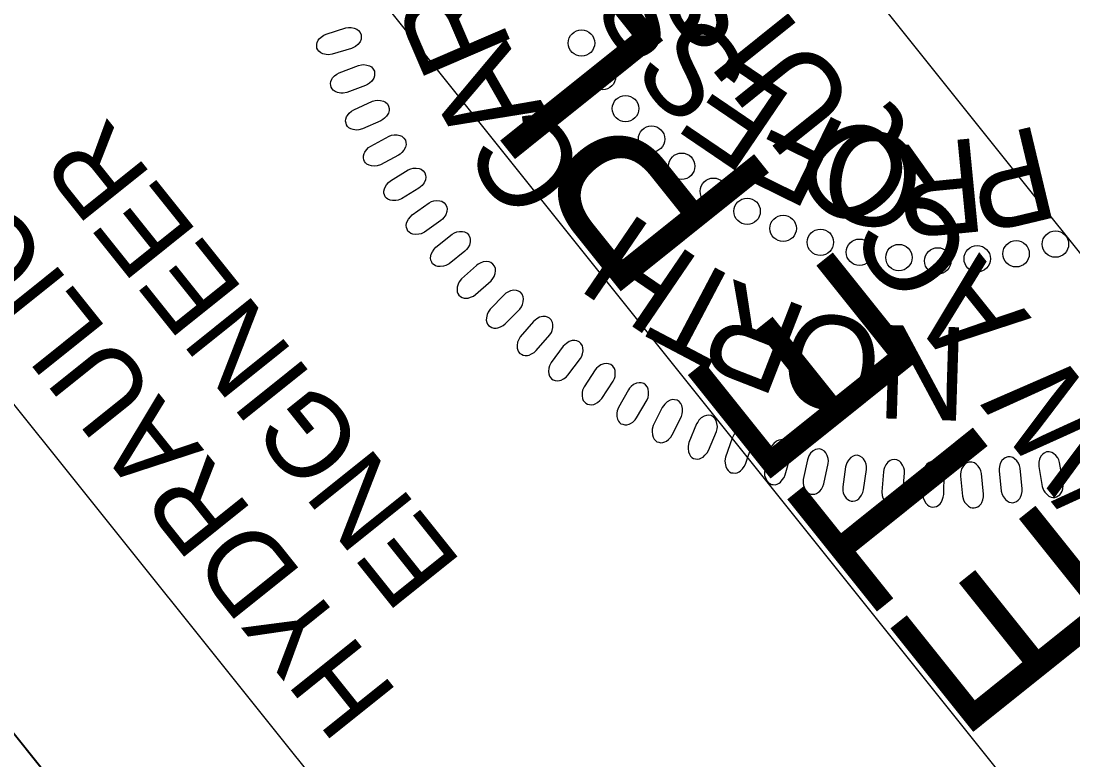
# Model space of a CAD drawing. Extents: x 473437 to 475344, y 504319 to 506318.
# Drawn here: x 473521.1 to 473584.9, y 505603.9 to 505648.7 of the extents above; entities that cross this region are included whole.
import ezdxf

# ---------------------------------------------------------------- set-up
doc = ezdxf.new("R2010")
doc.units = 0
for name, color, linetype in [('Sheet PE Seal Cell', 7, 'Continuous'), ('Sheet Plan CELL', 7, 'Continuous'), ('Sheet Sticker Incomplete CELL', 7, 'Continuous')]:
    doc.layers.add(name, color=color, linetype=linetype)

msp = doc.modelspace()

# ---------------------------------------------------------------- linework, layer by layer
at = {"layer": 'Sheet PE Seal Cell'}
for points in [[(473541.122, 505647.047), (473539.95, 505646.687), (473539.729, 505646.659), (473539.58, 505646.667), (473539.385, 505646.725), (473539.251, 505646.786), (473539.142, 505646.87), (473539.074, 505646.958), (473539.021, 505647.059), (473539.008, 505647.172), (473539.002, 505647.295), (473539.028, 505647.413), (473539.093, 505647.543), (473539.151, 505647.623), (473539.274, 505647.731), (473539.429, 505647.841), (473539.575, 505647.909), (473540.774, 505648.285), (473540.943, 505648.313), (473541.089, 505648.311), (473541.268, 505648.272), (473541.435, 505648.206), (473541.539, 505648.137), (473541.642, 505648.004), (473541.705, 505647.867), (473541.711, 505647.712), (473541.694, 505647.597), (473541.636, 505647.447), (473541.508, 505647.283), (473541.357, 505647.165), (473541.242, 505647.099)], [(473541.975, 505644.805), (473540.827, 505644.372), (473540.609, 505644.33), (473540.46, 505644.33), (473540.261, 505644.375), (473540.125, 505644.427), (473540.01, 505644.504), (473539.936, 505644.588), (473539.878, 505644.686), (473539.857, 505644.797), (473539.843, 505644.92), (473539.862, 505645.039), (473539.918, 505645.172), (473539.972, 505645.256), (473540.088, 505645.372), (473540.235, 505645.491), (473540.377, 505645.569), (473541.55, 505646.018), (473541.716, 505646.058), (473541.863, 505646.065), (473542.044, 505646.037), (473542.214, 505645.981), (473542.323, 505645.919), (473542.435, 505645.793), (473542.506, 505645.659), (473542.521, 505645.506), (473542.511, 505645.391), (473542.463, 505645.237), (473542.347, 505645.065), (473542.202, 505644.938), (473542.091, 505644.865)], [(473542.896, 505642.66), (473541.777, 505642.156), (473541.562, 505642.1), (473541.413, 505642.09), (473541.212, 505642.122), (473541.073, 505642.166), (473540.954, 505642.235), (473540.874, 505642.315), (473540.809, 505642.409), (473540.782, 505642.519), (473540.76, 505642.641), (473540.772, 505642.76), (473540.82, 505642.896), (473540.868, 505642.984), (473540.977, 505643.107), (473541.116, 505643.235), (473541.252, 505643.322), (473542.395, 505643.844), (473542.559, 505643.893), (473542.704, 505643.909), (473542.886, 505643.893), (473543.06, 505643.848), (473543.173, 505643.793), (473543.292, 505643.674), (473543.371, 505643.546), (473543.396, 505643.393), (473543.394, 505643.278), (473543.355, 505643.121), (473543.25, 505642.942), (473543.113, 505642.807), (473543.008, 505642.727)], [(473543.966, 505640.564), (473542.882, 505639.991), (473542.67, 505639.921), (473542.522, 505639.903), (473542.32, 505639.923), (473542.178, 505639.957), (473542.055, 505640.019), (473541.971, 505640.093), (473541.9, 505640.182), (473541.866, 505640.291), (473541.836, 505640.411), (473541.841, 505640.531), (473541.88, 505640.67), (473541.922, 505640.76), (473542.023, 505640.89), (473542.154, 505641.027), (473542.285, 505641.121), (473543.392, 505641.715), (473543.552, 505641.774), (473543.697, 505641.799), (473543.88, 505641.795), (473544.056, 505641.761), (473544.172, 505641.712), (473544.298, 505641.601), (473544.385, 505641.478), (473544.42, 505641.328), (473544.425, 505641.212), (473544.396, 505641.053), (473544.302, 505640.868), (473544.175, 505640.725), (473544.074, 505640.638)], [(473545.204, 505638.558), (473544.158, 505637.918), (473543.951, 505637.835), (473543.805, 505637.808), (473543.602, 505637.815), (473543.457, 505637.84), (473543.331, 505637.895), (473543.242, 505637.962), (473543.167, 505638.048), (473543.125, 505638.154), (473543.088, 505638.271), (473543.085, 505638.392), (473543.115, 505638.534), (473543.152, 505638.626), (473543.244, 505638.762), (473543.367, 505638.906), (473543.491, 505639.009), (473544.559, 505639.671), (473544.715, 505639.74), (473544.857, 505639.775), (473545.041, 505639.781), (473545.218, 505639.759), (473545.337, 505639.718), (473545.47, 505639.615), (473545.565, 505639.498), (473545.609, 505639.349), (473545.621, 505639.234), (473545.603, 505639.073), (473545.52, 505638.883), (473545.402, 505638.732), (473545.307, 505638.639)], [(473546.544, 505636.605), (473545.539, 505635.9), (473545.338, 505635.804), (473545.194, 505635.767), (473544.991, 505635.762), (473544.845, 505635.778), (473544.715, 505635.824), (473544.623, 505635.887), (473544.542, 505635.967), (473544.494, 505636.071), (473544.45, 505636.186), (473544.439, 505636.306), (473544.46, 505636.448), (473544.491, 505636.543), (473544.575, 505636.684), (473544.688, 505636.836), (473544.805, 505636.946), (473545.83, 505637.674), (473545.981, 505637.753), (473546.121, 505637.797), (473546.304, 505637.814), (473546.482, 505637.803), (473546.604, 505637.77), (473546.743, 505637.675), (473546.845, 505637.564), (473546.898, 505637.419), (473546.917, 505637.304), (473546.908, 505637.143), (473546.838, 505636.949), (473546.73, 505636.79), (473546.641, 505636.691)], [(473547.997, 505634.746), (473547.039, 505633.98), (473546.845, 505633.872), (473546.702, 505633.826), (473546.5, 505633.807), (473546.354, 505633.815), (473546.221, 505633.852), (473546.125, 505633.909), (473546.039, 505633.984), (473545.985, 505634.084), (473545.933, 505634.196), (473545.915, 505634.315), (473545.927, 505634.459), (473545.953, 505634.556), (473546.027, 505634.702), (473546.13, 505634.861), (473546.241, 505634.978), (473547.217, 505635.769), (473547.364, 505635.857), (473547.501, 505635.909), (473547.681, 505635.939), (473547.861, 505635.939), (473547.983, 505635.913), (473548.128, 505635.827), (473548.237, 505635.723), (473548.299, 505635.582), (473548.326, 505635.469), (473548.328, 505635.307), (473548.27, 505635.107), (473548.172, 505634.943), (473548.089, 505634.839)], [(473548.701, 505633.881), (473547.793, 505633.056), (473547.656, 505632.881), (473547.588, 505632.748), (473547.537, 505632.551), (473547.521, 505632.405), (473547.538, 505632.269), (473547.578, 505632.165), (473547.64, 505632.068), (473547.73, 505631.999), (473547.832, 505631.93), (473547.947, 505631.893), (473548.091, 505631.883), (473548.19, 505631.892), (473548.346, 505631.943), (473548.52, 505632.019), (473548.652, 505632.11), (473549.588, 505632.949), (473549.698, 505633.08), (473549.771, 505633.207), (473549.829, 505633.38), (473549.857, 505633.558), (473549.851, 505633.683), (473549.789, 505633.84), (473549.704, 505633.964), (473549.573, 505634.048), (473549.466, 505634.091), (473549.307, 505634.118), (473549.101, 505634.093), (473548.923, 505634.022), (473548.807, 505633.957)], [(473550.383, 505632.104), (473549.529, 505631.224), (473549.402, 505631.04), (473549.343, 505630.904), (473549.305, 505630.704), (473549.298, 505630.557), (473549.323, 505630.422), (473549.371, 505630.32), (473549.437, 505630.228), (473549.532, 505630.164), (473549.638, 505630.102), (473549.755, 505630.072), (473549.899, 505630.071), (473549.998, 505630.087), (473550.151, 505630.147), (473550.318, 505630.234), (473550.446, 505630.333), (473551.326, 505631.23), (473551.428, 505631.367), (473551.493, 505631.498), (473551.54, 505631.675), (473551.557, 505631.854), (473551.542, 505631.978), (473551.472, 505632.131), (473551.378, 505632.25), (473551.243, 505632.325), (473551.133, 505632.362), (473550.973, 505632.379), (473550.769, 505632.341), (473550.596, 505632.259), (473550.484, 505632.186)], [(473552.158, 505630.475), (473551.361, 505629.543), (473551.247, 505629.352), (473551.195, 505629.212), (473551.17, 505629.01), (473551.173, 505628.864), (473551.206, 505628.73), (473551.26, 505628.632), (473551.332, 505628.543), (473551.43, 505628.486), (473551.54, 505628.431), (473551.659, 505628.408), (473551.804, 505628.416), (473551.901, 505628.438), (473552.049, 505628.508), (473552.211, 505628.605), (473552.332, 505628.712), (473553.154, 505629.662), (473553.248, 505629.805), (473553.305, 505629.94), (473553.34, 505630.12), (473553.345, 505630.299), (473553.323, 505630.423), (473553.243, 505630.57), (473553.142, 505630.682), (473553.003, 505630.749), (473552.891, 505630.78), (473552.73, 505630.786), (473552.529, 505630.736), (473552.361, 505630.643), (473552.254, 505630.563)], [(473553.967, 505628.97), (473553.23, 505627.99), (473553.128, 505627.792), (473553.085, 505627.648), (473553.073, 505627.446), (473553.085, 505627.3), (473553.127, 505627.169), (473553.186, 505627.073), (473553.264, 505626.99), (473553.365, 505626.938), (473553.479, 505626.891), (473553.599, 505626.876), (473553.742, 505626.893), (473553.838, 505626.92), (473553.982, 505627), (473554.137, 505627.107), (473554.251, 505627.221), (473555.013, 505628.221), (473555.097, 505628.37), (473555.145, 505628.508), (473555.169, 505628.69), (473555.163, 505628.869), (473555.133, 505628.991), (473555.044, 505629.134), (473554.936, 505629.239), (473554.793, 505629.297), (473554.68, 505629.32), (473554.518, 505629.317), (473554.321, 505629.253), (473554.159, 505629.15), (473554.057, 505629.065)], [(473555.91, 505627.536), (473555.236, 505626.511), (473555.146, 505626.308), (473555.113, 505626.162), (473555.113, 505625.959), (473555.134, 505625.813), (473555.184, 505625.685), (473555.25, 505625.594), (473555.332, 505625.516), (473555.437, 505625.47), (473555.553, 505625.431), (473555.673, 505625.423), (473555.816, 505625.448), (473555.91, 505625.482), (473556.048, 505625.57), (473556.197, 505625.687), (473556.304, 505625.808), (473557, 505626.854), (473557.075, 505627.008), (473557.114, 505627.149), (473557.127, 505627.332), (473557.11, 505627.51), (473557.073, 505627.63), (473556.974, 505627.766), (473556.86, 505627.865), (473556.714, 505627.914), (473556.598, 505627.93), (473556.438, 505627.917), (473556.245, 505627.841), (473556.09, 505627.728), (473555.993, 505627.636)], [(473557.922, 505626.328), (473557.314, 505625.262), (473557.238, 505625.053), (473557.213, 505624.906), (473557.227, 505624.703), (473557.256, 505624.56), (473557.314, 505624.435), (473557.385, 505624.349), (473557.473, 505624.276), (473557.58, 505624.238), (473557.699, 505624.204), (473557.819, 505624.204), (473557.96, 505624.238), (473558.051, 505624.278), (473558.184, 505624.375), (473558.325, 505624.501), (473558.423, 505624.628), (473559.053, 505625.716), (473559.118, 505625.874), (473559.148, 505626.017), (473559.15, 505626.201), (473559.122, 505626.377), (473559.077, 505626.495), (473558.97, 505626.625), (473558.85, 505626.716), (473558.701, 505626.755), (473558.585, 505626.764), (473558.425, 505626.741), (473558.237, 505626.653), (473558.09, 505626.53), (473558, 505626.433)], [(473559.974, 505625.257), (473559.433, 505624.156), (473559.37, 505623.943), (473559.356, 505623.794), (473559.381, 505623.593), (473559.421, 505623.451), (473559.486, 505623.33), (473559.562, 505623.248), (473559.654, 505623.181), (473559.764, 505623.15), (473559.884, 505623.124), (473560.004, 505623.131), (473560.142, 505623.175), (473560.231, 505623.22), (473560.357, 505623.324), (473560.49, 505623.46), (473560.581, 505623.593), (473561.141, 505624.717), (473561.196, 505624.88), (473561.217, 505625.025), (473561.206, 505625.207), (473561.167, 505625.383), (473561.115, 505625.496), (473561.001, 505625.619), (473560.875, 505625.703), (473560.724, 505625.733), (473560.608, 505625.735), (473560.45, 505625.701), (473560.268, 505625.602), (473560.128, 505625.47), (473560.044, 505625.367)], [(473562.067, 505624.265), (473561.597, 505623.131), (473561.547, 505622.914), (473561.542, 505622.766), (473561.58, 505622.566), (473561.628, 505622.427), (473561.701, 505622.311), (473561.782, 505622.234), (473561.878, 505622.172), (473561.989, 505622.148), (473562.111, 505622.129), (473562.231, 505622.144), (473562.366, 505622.197), (473562.452, 505622.247), (473562.571, 505622.359), (473562.696, 505622.503), (473562.777, 505622.641), (473563.266, 505623.799), (473563.31, 505623.964), (473563.322, 505624.11), (473563.301, 505624.292), (473563.251, 505624.464), (473563.192, 505624.575), (473563.069, 505624.691), (473562.939, 505624.766), (473562.786, 505624.787), (473562.67, 505624.781), (473562.514, 505624.737), (473562.339, 505624.626), (473562.208, 505624.487), (473562.131, 505624.378)], [(473564.219, 505623.403), (473563.821, 505622.243), (473563.785, 505622.023), (473563.789, 505621.874), (473563.839, 505621.677), (473563.896, 505621.542), (473563.976, 505621.43), (473564.062, 505621.358), (473564.162, 505621.303), (473564.275, 505621.285), (473564.397, 505621.275), (473564.516, 505621.297), (473564.647, 505621.358), (473564.73, 505621.414), (473564.842, 505621.534), (473564.956, 505621.684), (473565.03, 505621.828), (473565.445, 505623.014), (473565.479, 505623.182), (473565.482, 505623.329), (473565.448, 505623.508), (473565.388, 505623.676), (473565.322, 505623.784), (473565.193, 505623.891), (473565.058, 505623.959), (473564.904, 505623.97), (473564.788, 505623.956), (473564.636, 505623.904), (473564.468, 505623.781), (473564.346, 505623.633), (473564.276, 505623.521)], [(473566.527, 505622.688), (473566.202, 505621.504), (473566.18, 505621.283), (473566.193, 505621.135), (473566.257, 505620.941), (473566.322, 505620.81), (473566.409, 505620.703), (473566.499, 505620.637), (473566.602, 505620.588), (473566.715, 505620.578), (473566.838, 505620.575), (473566.955, 505620.605), (473567.083, 505620.673), (473567.161, 505620.734), (473567.266, 505620.861), (473567.371, 505621.018), (473567.435, 505621.166), (473567.775, 505622.376), (473567.798, 505622.546), (473567.792, 505622.692), (473567.748, 505622.87), (473567.676, 505623.034), (473567.604, 505623.137), (473567.468, 505623.236), (473567.329, 505623.294), (473567.174, 505623.296), (473567.061, 505623.275), (473566.911, 505623.213), (473566.751, 505623.081), (473566.639, 505622.925), (473566.576, 505622.808)], [(473568.786, 505622.087), (473568.537, 505620.886), (473568.529, 505620.664), (473568.551, 505620.516), (473568.627, 505620.328), (473568.699, 505620.201), (473568.793, 505620.099), (473568.887, 505620.04), (473568.993, 505619.997), (473569.107, 505619.994), (473569.23, 505619.999), (473569.345, 505620.035), (473569.468, 505620.112), (473569.542, 505620.178), (473569.639, 505620.311), (473569.734, 505620.474), (473569.789, 505620.627), (473570.052, 505621.855), (473570.064, 505622.025), (473570.048, 505622.171), (473569.993, 505622.345), (473569.912, 505622.505), (473569.833, 505622.603), (473569.691, 505622.694), (473569.549, 505622.743), (473569.395, 505622.734), (473569.282, 505622.708), (473569.137, 505622.636), (473568.986, 505622.494), (473568.884, 505622.332), (473568.828, 505622.211)], [(473571.105, 505621.653), (473570.931, 505620.439), (473570.937, 505620.216), (473570.969, 505620.07), (473571.056, 505619.887), (473571.136, 505619.765), (473571.236, 505619.67), (473571.334, 505619.615), (473571.442, 505619.58), (473571.556, 505619.584), (473571.679, 505619.596), (473571.791, 505619.64), (473571.909, 505619.725), (473571.98, 505619.795), (473572.067, 505619.934), (473572.152, 505620.103), (473572.196, 505620.257), (473572.382, 505621.501), (473572.384, 505621.671), (473572.359, 505621.816), (473572.293, 505621.986), (473572.202, 505622.141), (473572.117, 505622.234), (473571.97, 505622.315), (473571.824, 505622.356), (473571.671, 505622.337), (473571.56, 505622.303), (473571.42, 505622.223), (473571.278, 505622.072), (473571.186, 505621.903), (473571.138, 505621.779)], [(473582.838, 505621.67), (473583.047, 505620.461), (473583.122, 505620.251), (473583.197, 505620.122), (473583.337, 505619.975), (473583.451, 505619.883), (473583.575, 505619.824), (473583.685, 505619.803), (473583.799, 505619.802), (473583.906, 505619.841), (473584.019, 505619.891), (473584.112, 505619.967), (473584.197, 505620.084), (473584.243, 505620.172), (473584.284, 505620.331), (473584.312, 505620.519), (473584.307, 505620.68), (473584.099, 505621.919), (473584.048, 505622.082), (473583.98, 505622.212), (473583.864, 505622.354), (473583.73, 505622.472), (473583.62, 505622.534), (473583.455, 505622.567), (473583.305, 505622.56), (473583.164, 505622.495), (473583.07, 505622.429), (473582.961, 505622.308), (473582.873, 505622.121), (473582.837, 505621.933), (473582.83, 505621.8)], [(473573.4, 505621.361), (473573.303, 505620.138), (473573.323, 505619.916), (473573.364, 505619.773), (473573.462, 505619.595), (473573.55, 505619.478), (473573.656, 505619.39), (473573.757, 505619.342), (473573.867, 505619.313), (473573.98, 505619.324), (473574.102, 505619.344), (473574.211, 505619.395), (473574.323, 505619.486), (473574.389, 505619.561), (473574.469, 505619.705), (473574.542, 505619.879), (473574.578, 505620.037), (473574.684, 505621.289), (473574.675, 505621.459), (473574.642, 505621.602), (473574.565, 505621.768), (473574.464, 505621.916), (473574.374, 505622.004), (473574.222, 505622.076), (473574.075, 505622.107), (473573.922, 505622.079), (473573.814, 505622.038), (473573.679, 505621.949), (473573.547, 505621.789), (473573.465, 505621.616), (473573.426, 505621.489)], [(473575.803, 505621.218), (473575.783, 505619.991), (473575.817, 505619.771), (473575.867, 505619.631), (473575.976, 505619.459), (473576.071, 505619.348), (473576.182, 505619.267), (473576.286, 505619.225), (473576.398, 505619.203), (473576.51, 505619.221), (473576.63, 505619.25), (473576.736, 505619.307), (473576.842, 505619.405), (473576.904, 505619.484), (473576.973, 505619.633), (473577.036, 505619.811), (473577.061, 505619.97), (473577.089, 505621.226), (473577.07, 505621.397), (473577.027, 505621.537), (473576.94, 505621.698), (473576.83, 505621.839), (473576.734, 505621.92), (473576.578, 505621.983), (473576.43, 505622.005), (473576.279, 505621.968), (473576.174, 505621.92), (473576.045, 505621.822), (473575.923, 505621.655), (473575.852, 505621.476), (473575.821, 505621.347)], [(473578.085, 505621.091), (473578.209, 505619.871), (473578.269, 505619.656), (473578.334, 505619.523), (473578.463, 505619.365), (473578.571, 505619.266), (473578.69, 505619.198), (473578.798, 505619.169), (473578.912, 505619.161), (473579.022, 505619.191), (473579.138, 505619.234), (473579.236, 505619.303), (473579.33, 505619.413), (473579.381, 505619.499), (473579.433, 505619.654), (473579.475, 505619.839), (473579.481, 505620), (473579.361, 505621.251), (473579.322, 505621.418), (473579.263, 505621.552), (473579.157, 505621.701), (473579.032, 505621.829), (473578.927, 505621.898), (473578.765, 505621.942), (473578.614, 505621.947), (473578.469, 505621.892), (473578.37, 505621.832), (473578.254, 505621.72), (473578.152, 505621.539), (473578.103, 505621.354), (473578.087, 505621.222)], [(473580.423, 505621.407), (473580.557, 505620.188), (473580.618, 505619.974), (473580.685, 505619.841), (473580.815, 505619.684), (473580.923, 505619.585), (473581.043, 505619.518), (473581.152, 505619.49), (473581.266, 505619.483), (473581.375, 505619.515), (473581.49, 505619.558), (473581.588, 505619.628), (473581.681, 505619.739), (473581.732, 505619.825), (473581.783, 505619.981), (473581.823, 505620.166), (473581.827, 505620.327), (473581.698, 505621.577), (473581.657, 505621.743), (473581.597, 505621.877), (473581.491, 505622.025), (473581.364, 505622.152), (473581.259, 505622.221), (473581.096, 505622.263), (473580.945, 505622.267), (473580.801, 505622.211), (473580.703, 505622.15), (473580.587, 505622.037), (473580.487, 505621.856), (473580.439, 505621.67), (473580.424, 505621.537)]]:
    msp.add_lwpolyline(points, close=True, dxfattribs=at)
for centre in [(473555.076, 505647.372), (473556.351, 505645.333), (473557.749, 505643.392), (473559.329, 505641.546), (473561.157, 505639.898), (473563.084, 505638.381), (473565.13, 505637.162), (473567.317, 505636.127), (473569.575, 505635.282), (473583.843, 505635.172), (473571.944, 505634.679), (473574.345, 505634.356), (473581.455, 505634.587), (473576.702, 505634.151), (473579.097, 505634.282)]:
    msp.add_circle(centre, 0.801, dxfattribs=at)
at = {"layer": 'Sheet Plan CELL'}
msp.add_line((473610.144, 505493.633), (473485.131, 505649.796), dxfattribs=at)
msp.add_line((473610.144, 505493.633), (473485.131, 505649.796), dxfattribs=at)
for points in [[(473557.377, 505579.55), (473494.89, 505657.607), (473582.726, 505727.92), (473645.22, 505649.853)], [(473590.557, 505477.958), (473465.55, 505634.173), (473485.131, 505649.796), (473610.144, 505493.633)]]:
    msp.add_lwpolyline(points, close=True, dxfattribs=at)
at = {"layer": 'Sheet Sticker Incomplete CELL'}
msp.add_lwpolyline([(473647.22, 505557.313), (473628.873, 505542.629), (473537.02, 505657.398), (473555.367, 505672.082)], close=True, dxfattribs=at)

# ---------------------------------------------------------------- texts
at = {"layer": 'Sheet PE Seal Cell'}
for s, rotation, p in [('R', 113.28019, (473550.964, 505647.055)), ('S', 122.02046, (473563.113, 505648.502)), ('S', 129.96025, (473565.605, 505645.551)), ('A', 119.76954, (473552.972, 505643.275)), ('E', 145.83985, (473568.083, 505643.99)), ('C', 126.2589, (473555.669, 505639.573)), ('F', 153.77965, (473571.403, 505642.304)), ('O', 169.65924, (473576.163, 505641.379)), ('P', 193.47864, (473582.901, 505642.416)), ('R', 185.53884, (473579.222, 505641.632)), ('H', 145.72697, (473562.454, 505634.109)), ('T', 152.21633, (473565.541, 505632.508)), ('R', 158.70569, (473569.051, 505631.192)), ('O', 171.6844, (473573.587, 505630.371)), ('N', 178.17375, (473578.61, 505630.105))]:
    msp.add_text(s, height=5.669, rotation=rotation, dxfattribs=at).set_placement(p)
at = {"layer": 'Sheet Plan CELL'}
for s, p in [('ENGINEER', (473547.888, 505615.792)), ('HYDRAULICS', (473544.022, 505607.879))]:
    msp.add_text(s, height=5.0001, rotation=128.67123, dxfattribs=at).set_placement(p)
at = {"layer": 'Sheet Sticker Incomplete CELL'}
for s, height, p in [('INCOMPLETE PLANS', 11.52, (473632.493, 505556.99)), ('DO NOT USE FOR R/W ACQUISITION', 5.76, (473635.889, 505563.87))]:
    msp.add_text(s, height=height, rotation=128.67122, dxfattribs=at).set_placement(p)

doc.saveas('drawing.dxf')
